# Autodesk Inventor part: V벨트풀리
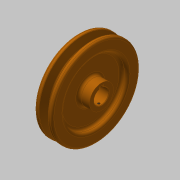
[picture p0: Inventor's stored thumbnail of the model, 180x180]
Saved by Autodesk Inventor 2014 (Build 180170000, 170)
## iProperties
Created: 2015-11
Part Number: V벨트풀리
Material: 강철, 탄소
Document SubType Name: Modeling
Designer: mduedu
Density: 1 g/cm^3
Appearance: 주황색
Author: mduedu
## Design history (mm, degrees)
sketch "스케치1"
  geometry: L1 (-9.5, 0)-(9.5, 0); L2 (0, 0)-(0, 47.7); L3 (-4.877, 47.7)-(-9.5, 47.7); L4 (-9.5, 47.7)-(-9.5, 0); L5 (0, 38.7)-(-1.953, 38.7); L6 (-1.953, 38.7)-(-4.877, 47.7); L7 (4.877, 47.7)-(9.5, 47.7); L8 (9.5, 47.7)-(9.5, 0); L9 (0, 38.7)-(1.953, 38.7); L10 (1.953, 38.7)-(4.877, 47.7); L11 (-9.5, 45)-(9.5, 45); 3 further points
  constraints: 22 end point, 7 point on line, 4 perpendicular, 3 symmetric about line, 1 coincident, 1 horizontal, 1 horizontal alignment, 1 midpoint, 1 vertical
  dimensions: "d0" = 19 distance of L1.start L1.end; "d2" = 95.4 diameter of L2.end L1 (derived); "d3" = 36 deg angle of L10 L6; "d4" = 6.3 distance between parallel lines of L11 L9; "d5" = 2.7 distance between parallel lines of L7 L11; "d6" = 8 distance of point (4, 45) point (-4, 45); "d7" = 90 diameter of L11 L1
revolve "회전1" sketch "스케치1" stored, may be unused: angle "d8" = 90 deg
sketch "스케치2"
  geometry: C1 r 34 at (0, 0); C2 r 13 at (0, 0); 1 further point
  constraints: 2 centre point, 2 coincident
  dimensions: "d9" = 68 diameter of C1; "d10" = 26 diameter of C2
extrude "돌출1" cut sketch "스케치2" distance "d11" = 6; taper "d12" = 0 deg
extrude "돌출3" join sketch "스케치2" distance "d37" = 6; taper "d38" = 0 deg
fillet "모깎기1" dims "d13" = 3
fillet "모깎기2" dims "d14" = 3
fillet "모깎기3" dims "d15" = 1, "d16" = 0.5, "d17" = 2
hole "구멍1" diameter "d20" = 16; stored, may be unused: countersink angle "d24" = 90 deg, drill point angle "d26" = 118 deg; dims "d21" = 6, "d22" = 4, "d23" = 2, "d25" = 8, "d53" = 10, "d54" = 10
sketch "스케치3"
  geometry: L1 (-2.5, 0)-(2.5, 0); L2 (2.5, 0)-(2.5, 10.3); L3 (2.5, 10.3)-(-2.5, 10.3); L4 (-2.5, 10.3)-(-2.5, 0); 2 further points
  constraints: 8 end point, 2 parallel, 1 coincident, 1 horizontal, 1 midpoint, 1 perpendicular
  dimensions: "d27" = 5 distance of L2.end L3.end; "d29" = 10.3 distance of L3.end L1.start
extrude "돌출2" cut sketch "스케치3" stored distance "d30" = 6; taper "d31" = 0 deg
node "작업 평면1"
sketch "스케치4"
  geometry: L1 (19, -37)-(19, 37) reference; 2 further points
  constraints: 1 horizontal alignment
  dimensions: "d52" = 22 distance from line of L1 point (-3, 0)
hole "구멍2" sketch "스케치4" at (-3, 0) diameter "d42" = 2.459; stored, may be unused: countersink angle "d46" = 90 deg, drill point angle "d48" = 118 deg; dims "d43" = 6, "d44" = 4, "d45" = 2, "d47" = 8
chamfer "모따기3" distance "d58" = 0.5; stored, may be unused: second distance "d59" = 2, angle "d60" = 45 deg
node "솔리드1"
mirror "대칭1"
